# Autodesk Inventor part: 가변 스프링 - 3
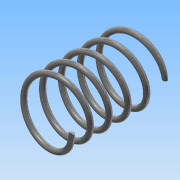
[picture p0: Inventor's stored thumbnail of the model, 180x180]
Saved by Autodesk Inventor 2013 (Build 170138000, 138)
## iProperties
Created: 2016-01
Part Number: 가변 스프링 - 3
Material: 스테인리스강
Document SubType Name: Modeling
Designer: Administrator
Mass: 8.67 g
Surface Area: 21.7147 cm^2
Volume: 1.07302 cm^3
Density: 8.08 g/cm^3
Author: Administrator
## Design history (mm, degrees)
sketch "스케치1"
  geometry: L1 (0, 0)-(11, 0); L2 (11, 0)-(11, 36.411); L3 (11, 36.411)-(0, 36.411); L4 (0, 36.411)-(0, 0); C1 r 1 at (11, 0)
  constraints: 8 end point, 2 parallel, 1 centre point, 1 coincident, 1 horizontal, 1 perpendicular
  dimensions: "d0" = 2 diameter of C1; "d2" = 22 diameter of L2 L4; "d3" = 36.4112 distance between parallel lines of L1 L3 (derived)
feature "코일1" sketch "스케치1" pitch "d4" = 10; turns "d6" = 5; dims "d5" = 36.4112 (= d3), "d7" = 0, angle "d8" = 90 deg, angle "d9" = 90 deg, "d10" = 0, "d11" = 0
feature "분할1"
node "작업 평면1"
feature "분할2"
node "솔리드1"
other parameters: "d12" = 90 deg
